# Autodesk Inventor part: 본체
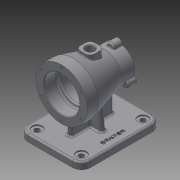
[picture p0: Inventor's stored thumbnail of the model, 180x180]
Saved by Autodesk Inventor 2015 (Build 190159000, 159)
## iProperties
Created: 2021-10
Part Number: 본체
Material: 일반
Document SubType Name: Modeling
Designer: pc-04
Density: 1 g/cm^3
Appearance: 기본값
Mass: 453.009 g
Surface Area: 899.649 cm^2
Volume: 453.009 cm^3
Author: pc-04
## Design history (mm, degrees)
sketch "스케치1"
  geometry: L1 (0, 50)-(0, -50); L2 (0, 50)-(45, 50); L3 (45, 50)-(45, 30); L4 (45, 30)-(29, -27); L5 (29, -27)-(29, -50); L6 (29, -50)-(0, -50); 2 further points
  constraints: 12 end point, 2 coincident, 2 perpendicular, 1 horizontal, 1 midpoint, 1 parallel, 1 vertical
  dimensions: "d0" = 90 diameter of L3 L1; "d1" = 20 distance of L2.end L3.end; "d2" = 23 distance of L4.end L5.end; "d3" = 58 diameter of L5 L1; "d4" = 100 distance of L1.start L1.end
revolve "회전1" sketch "스케치1" stored, may be unused: angle "d5" = 90 deg
sketch "스케치2"
  geometry: L1 (0, 50)-(31, 50); L2 (-45, 50)-(45, 50) reference; L3 (31, 30)-(31, 50); L4 (28, 27)-(28, 27); L5 (25, 24)-(25, -17); L6 (22, -20)-(22, -20); L7 (19, -23)-(19, -50); L8 (19, -50)-(0, -50); L9 (0, 50)-(0, -50); A1 r 3 centre (28, 30) between (28, 27) and (31, 30); A2 r 3 centre (28, 24) between (28, 27) and (25, 24); A3 r 3 centre (22, -17) between (22, -20) and (25, -17); A4 r 3 centre (22, -23) between (22, -20) and (19, -23); 6 further points
  constraints: 16 end point, 9 point on line, 8 point on circle, 8 tangent, 5 perpendicular, 4 centre point, 3 equal radius, 1 coincident, 1 horizontal, 1 midpoint, 1 vertical
  dimensions: "d6" = 23 distance of point (31, 27) L1.end; "d7" = 47 distance of point (25, 27) point (25, -20); "d8" = 30 distance of point (19, -20) L7.end; "d9" = 62 diameter of L3 L9; "d10" = 50 diameter of L5 L9; "d11" = 38 diameter of L7 L9; "d12" = 3 radius of A1
revolve "회전2" sketch "스케치2" stored, may be unused: angle "d13" = 90 deg
chamfer "모따기1" distance "d14" = 1; stored, may be unused: second distance "d15" = 2, angle "d16" = 45 deg
chamfer "모따기2" distance "d17" = 1; stored, may be unused: second distance "d18" = 2, angle "d19" = 45 deg
sketch "스케치3" dims "d20" = 58
  geometry: C1 r 7 at (0, 29); 2 further points
  constraints: 2 vertical alignment, 1 centre point, 1 coincident, 2 other
  dimensions: "d21" = 14 diameter of C1
extrude "돌출1" join sketch "스케치3" distance "d22" = 15; taper "d23" = 0 deg
fillet "모깎기1" dims "d24" = 1, "d25" = 3
sketch "스케치4"
  geometry: 2 further points
hole "구멍1" sketch "스케치4" at (0, 0) diameter "d26" = 3.242; stored, may be unused: countersink angle "d30" = 90 deg, drill point angle "d32" = 118 deg; dims "d27" = 9, "d28" = 4, "d29" = 2, "d31" = 11
node "작업 평면1"
sketch "스케치5"
  geometry: L1 (12.5, 12.5)-(-12.5, 12.5); L2 (-12.5, 12.5)-(-12.5, -12.5); L3 (-12.5, -12.5)-(12.5, -12.5); L4 (12.5, -12.5)-(12.5, 12.5); 3 further points
  constraints: 8 end point, 2 midpoint, 2 parallel, 1 horizontal, 1 horizontal alignment, 1 perpendicular, 1 vertical alignment
  dimensions: "d37" = 25 distance of L2.end L3.end; "d38" = 25 distance of L3.end L1.start
extrude "돌출2" join sketch "스케치5" stored distance "d39" = 15; taper "d40" = 0 deg
fillet "모깎기2" dims "d41" = 8
fillet "모깎기3" dims "d42" = 1
sketch "스케치6"
  geometry: C1 r 7.5 at (0, 0); 1 further point
  constraints: 1 centre point, 1 coincident
  dimensions: "d43" = 15 diameter of C1
extrude "돌출3" cut sketch "스케치6" stored distance "d44" = 15; taper "d45" = 0 deg
chamfer "모따기3" distance "d46" = 1; stored, may be unused: second distance "d47" = 2, angle "d48" = 45 deg
sketch "스케치7" dims "d49" = 80
  geometry: 3 further points
  constraints: 2 vertical alignment, 1 coincident, 2 other
hole "구멍2" sketch "스케치7" at (0, 40) diameter "d50" = 3.242; stored, may be unused: countersink angle "d54" = 90 deg, drill point angle "d56" = 118 deg; dims "d51" = 9, "d52" = 4, "d53" = 2, "d55" = 11
node "작업 평면2"
sketch "스케치8"
  geometry: L1 (55, 70)-(-55, 70); L2 (-55, 70)-(-55, -70); L3 (-55, -70)-(55, -70); L4 (55, -70)-(55, 70); 3 further points
  constraints: 8 end point, 2 midpoint, 2 parallel, 1 horizontal, 1 horizontal alignment, 1 perpendicular, 1 vertical alignment
  dimensions: "d61" = 140 distance of L3.end L1.start; "d62" = 110 distance of L1.start L1.end
extrude "돌출4" join sketch "스케치8" distance "d63" = 12; taper "d64" = 0 deg
fillet "모깎기4" dims "d65" = 16
sketch "스케치9"
  geometry: L1 (55, -54)-(55, 54) reference; L2 (39, 70)-(-39, 70) reference; L3 (-39, -70)-(39, -70) reference; A1 r 16 centre (-39, 54) between (-39, 70) and (-55, 54) reference; 5 further points
  constraints: 1 coincident
  dimensions: "d66" = 16 distance from line of L1 point (39, 54); "d67" = 16 distance from line of L2 point (39, 54); "d68" = 108 distance of point (-39, -54) point (-39, 54); "d69" = 16 distance from line of L3 point (-39, -54); "d70" = 16 distance from line of L1 point (39, -54); "d71" = 78 distance of point (39, -54) point (-39, -54)
hole "구멍3" sketch "스케치9" at (-39, 54), (39, 54), (39, -54), (-39, -54) diameter "d72" = 9; stored, may be unused: countersink angle "d76" = 90 deg, drill point angle "d78" = 118 deg; dims "d73" = 9, "d74" = 18, "d75" = 2, "d77" = 12
sketch "스케치10"
  geometry: L1 (-4, -37)-(4, -37); L2 (4, -37)-(4, 37); L3 (4, 37)-(-4, 37); L4 (-4, 37)-(-4, -37); L5 (-24, -4)-(24, -4); L6 (24, -4)-(24, 4); L7 (24, 4)-(-24, 4); L8 (-24, 4)-(-24, -4); L9 (-39, -70)-(39, -70) reference; 3 further points
  constraints: 16 end point, 4 parallel, 2 horizontal, 2 midpoint, 2 perpendicular, 1 horizontal alignment, 1 vertical alignment
  dimensions: "d79" = 8 distance of L2.end L3.end; "d80" = 8 distance of L7.end L5.start; "d81" = 33 distance between parallel lines of L9 L1; "d82" = 74 distance of L3.end L1.start; "d83" = 24 distance from line of L8 point (0, 0); "d84" = 24 distance from line of L6 point (0, 0)
extrude "돌출5" join sketch "스케치10" stored distance "d85" = 2; taper "d86" = 0 deg
feature "면 기울기1" dims angle "d87" = 5 deg
feature "면 기울기2" dims angle "d88" = 5 deg
fillet "모깎기5" dims "d89" = 3
fillet "모깎기6" dims "d90" = 3, "d91" = 3
fillet "모깎기7" dims "d92" = 3
sketch "스케치11"
  geometry: L1 (39, 70)-(-39, 70) reference; L2 (55, -54)-(55, 54) reference; L3 (-39, -70)-(39, -70) reference; L4 (-55, 54)-(-55, -54) reference; C1 r 4.5 at (39, -54) reference; C2 r 4.5 at (-39, 54) reference; C3 r 4.5 at (39, 54) reference; C4 r 4.5 at (-39, -54) reference; A1 r 16 centre (-39, 54) between (-39, 70) and (-55, 54) reference; A2 r 16 centre (39, 54) between (55, 54) and (39, 70) reference; A3 r 16 centre (39, -54) between (39, -70) and (55, -54) reference; A4 r 16 centre (-39, -54) between (-55, -54) and (-39, -70) reference; 2 further points
  constraints: 1 horizontal alignment, 1 other
  dimensions: "d93" = 15 distance from line of L2 point (40, 0)
extrude "돌출6" join sketch "스케치11" distance "d94" = 0.5; taper "d95" = 0 deg
node "솔리드1"
pattern_circular "원형 패턴1" dims "d34" = 360 deg
pattern_circular "원형 패턴2" dims angle "d58" = 360 deg
node "투영된 루프1"
other parameters: "d36" = 45, "d60" = -82
